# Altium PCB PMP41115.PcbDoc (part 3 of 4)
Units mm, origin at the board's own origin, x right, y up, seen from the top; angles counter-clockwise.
Board outline 97.92 x 43.13 mm, 4 copper layers (Top Layer, Signal Layer 1, Signal Layer 2, Bottom Layer), stack 1.016 mm thick; 168 components, 122 nets, 522 pads, 2459 vias.
Unrouted connection lines stored in the file: 1.
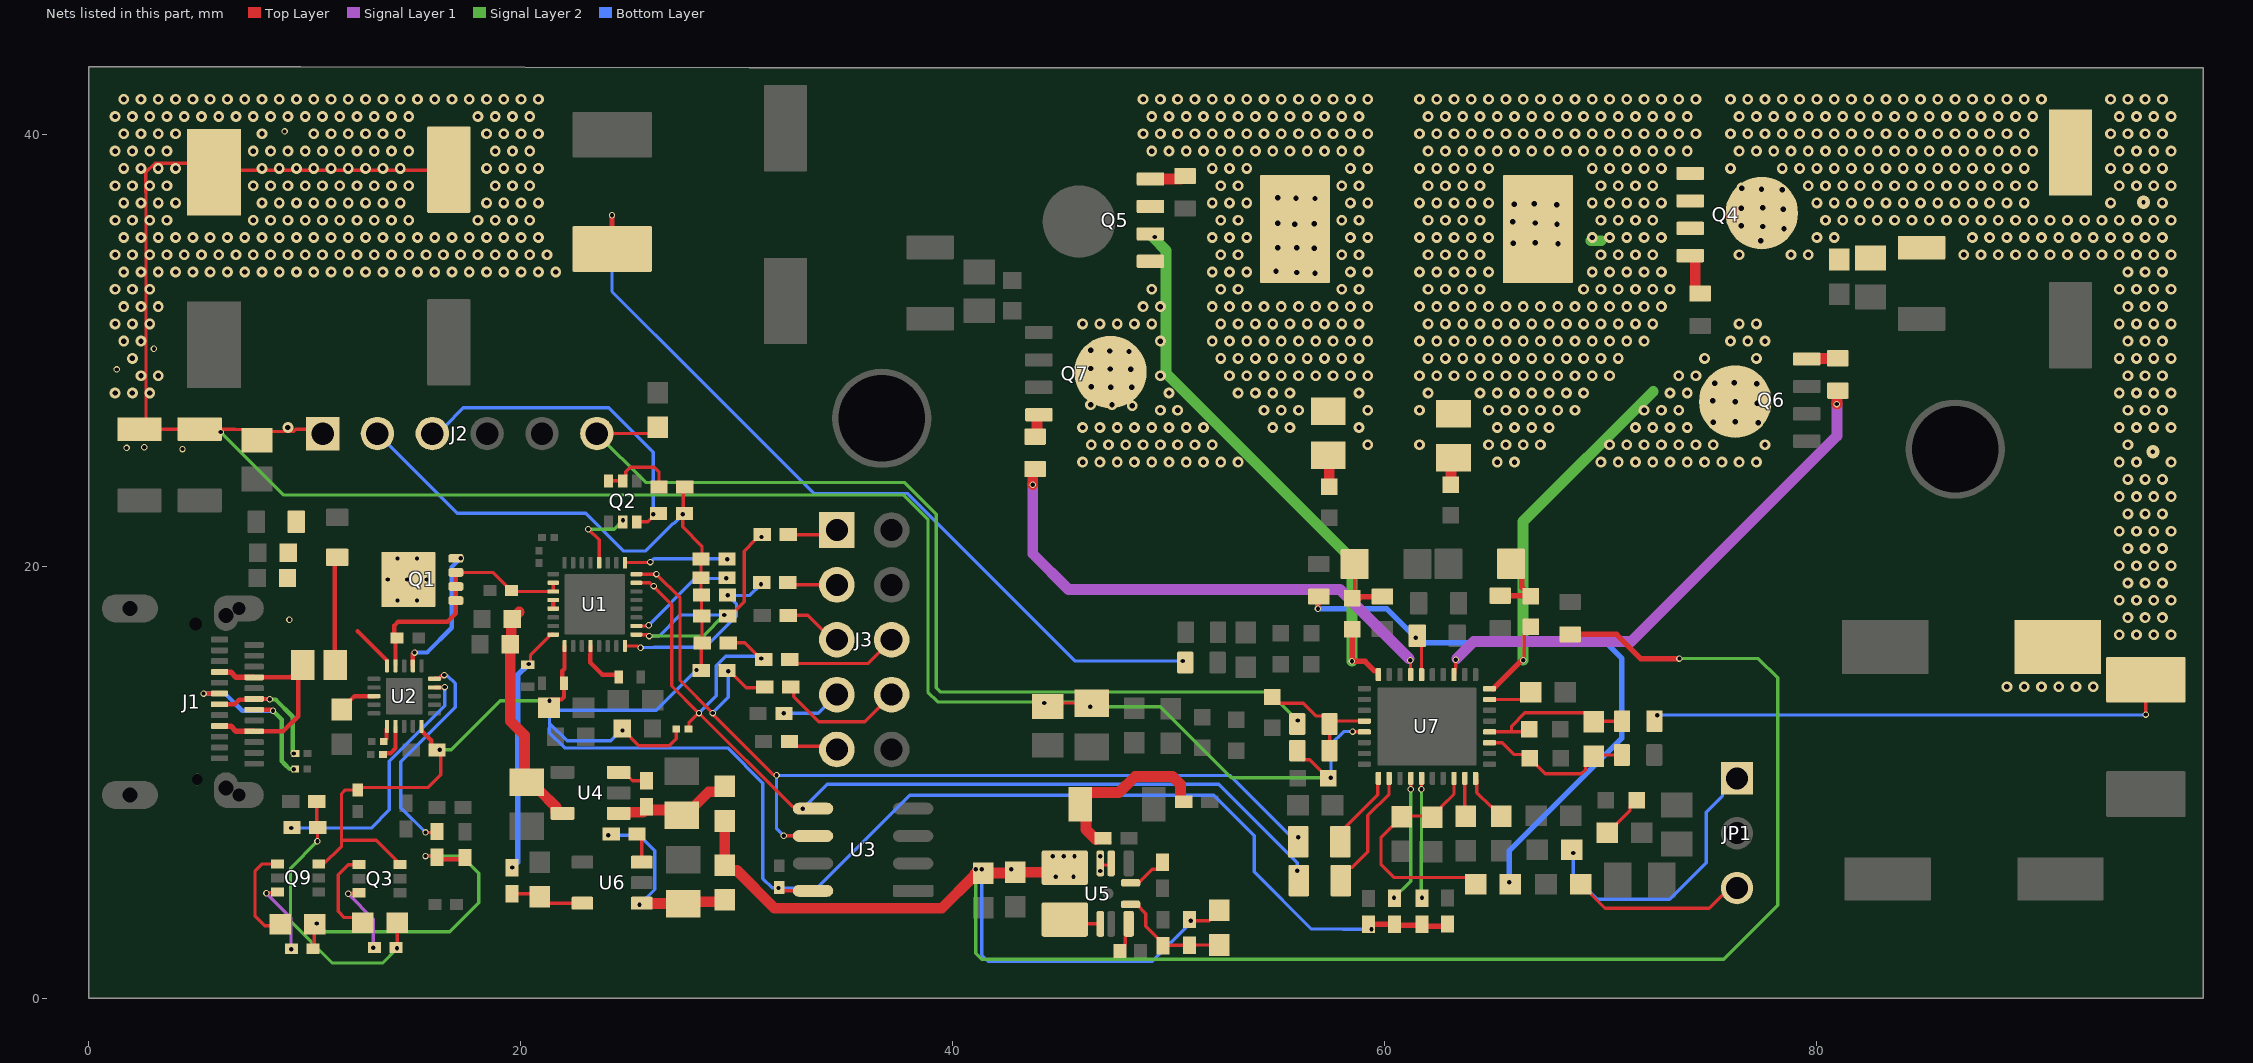
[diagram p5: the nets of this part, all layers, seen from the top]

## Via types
v1: diameter 0.5, hole 0.25, Top Layer to Bottom Layer, 2147 vias
v2: diameter 0.3, hole 0.2, Top Layer to Bottom Layer, tented both sides, 193 vias
v3: diameter 0.5, hole 0.25, Top Layer to Bottom Layer, tented both sides, 61 vias
v4: diameter 0.5, hole 0.2, Top Layer to Bottom Layer, 22 vias
v5: diameter 0.5, hole 0.2, Top Layer to Bottom Layer, tented both sides, 19 vias
v6: diameter 0.61, hole 0.203, Top Layer to Bottom Layer, tented both sides, 13 vias
v7: diameter 0.35, hole 0.2, Top Layer to Bottom Layer, tented both sides, 2 vias
v8: diameter 0.4, hole 0.2, Top Layer to Bottom Layer, tented both sides, 2 vias

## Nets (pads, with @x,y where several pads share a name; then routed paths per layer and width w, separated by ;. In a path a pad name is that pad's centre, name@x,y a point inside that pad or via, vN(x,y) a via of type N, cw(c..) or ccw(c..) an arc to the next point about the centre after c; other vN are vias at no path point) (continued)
I2Cc_SCL: R6.1 R64.2 R109.2 U1.16 U3.6 | length 46.7
  Top Layer w0.152: U1.16@25.36,19.632 25.361,19.633 26.288,19.633 v2(26.289,19.634) 27.381,18.542 27.381,14.707 v2@28.891,13.196 ; v2(28.895,13.2) 28.895,13.16 28.969,13.086 28.969,13.08 31.708,10.341 31.823,10.341 v2(31.852,10.312) ; R6.1@29.561,15.164 29.661,15.164 30.449,14.376 R109.2@31.013,14.376 ; v2(32.182,7.518) 32.188,7.512 32.874,7.512 U3.6@32.893,7.493 ; U3.6@32.87,7.687 33.051,7.506 U3.6@33.541,7.506 ; U3.6@33.985,7.518 U3.6@34.318,7.518
  Bottom Layer w0.152: v2@28.905,13.208 28.905,13.21 29.618,13.923 v2(29.618,15.142) ; v2@32.196,7.544 32.156,7.544 31.852,7.849 v2(31.852,10.312) 52.832,10.312 55.702,7.442 v2(56.007,7.442)
I2Cc_SDA: R7.1 R12.1 R60.2 R63.2 U1.15 U3.5 | length 47.5
  Top Layer w0.152: U1.15@25.476,19.228 25.984,19.228 27,18.212 27,14.453 v2@28.232,13.221 ; R12.1@27.768,12.458 27.793,12.483 27.793,12.757 28.232,13.196 v2@28.219,13.208 ; v2(28.26,13.2) 32.609,8.851 U3.5@33.06,8.851 ; R7.1@29.617,16.45 30.383,16.45 31.111,15.723 v2(31.14,15.723) ; v2(33.06,8.769) U3.5@33.06,8.851 ; U3.5@33.541,8.776 33.466,8.851 U3.5@33.06,8.851
  Bottom Layer w0.152: v2@28.245,13.208 28.268,13.208 29.058,13.998 29.058,15.392 29.491,15.826 30.997,15.826 31.1,15.723 v2(31.14,15.723) ; v2(33.06,8.769) 34.198,9.906 52.324,9.906 55.956,6.274 v2(55.956,5.893)
  other v2: 26.163,19.079
I2Ct_SCL: R3.1 R18.1 U1.9 | length 12.9
  Top Layer w0.152: U1.9@25.324,16.84 25.345,16.819 25.864,16.819 25.919,16.764 v2(25.959,16.764) ; R3.1@29.591,17.685 29.691,17.685 30.093,18.088 30.353,18.347 30.353,20.701 30.871,21.219 30.871,21.235 31.099,21.463 R18.1@31.115,21.463
  Signal Layer 2 w0.152: v2(25.959,16.764) 28.455,16.764 v2(29.432,17.741)
  Bottom Layer w0.152: v2(25.959,16.764) 26.416,16.764 27.393,17.741 v2(29.432,17.741)
  other v2: 31.155,21.353
I2Ct_SDA: R4.1 R20.1 U1.8 | length 8.8
  Top Layer w0.152: U1.8@24.835,16.307 25.437,16.307 25.487,16.256 v2@25.552,16.256 ; v2@25.512,16.231 v2(25.552,16.231) ; R20.1@31.048,19.228 R20.1@31.166,19.228
  Bottom Layer w0.152: v2(25.552,16.231) 26.153,16.231 26.175,16.253 28.546,16.253 29.997,17.704 29.997,18.242 v2@29.621,18.618 ; v2(29.592,18.647) 30.608,18.647 31.09,19.128 v2@31.09,19.177
  other v2: 31.13,19.169
I\2\C\c\_\I\R\Q\: R8.1 U1.17 | length 4.8
  Top Layer w0.152: U1.17@24.841,20.218 24.841,20.192 24.859,20.175 25.991,20.175 v2(26.01,20.193)
  Bottom Layer w0.152: v2(26.01,20.193) 26.02,20.193 26.173,20.345 v2@29.549,20.345
  other v2: 29.567,20.323
I\2\C\t\_\I\R\Q\: R5.1 U1.10 | length 5.2
  Top Layer w0.152: U1.10@25.36,17.232 25.853,17.232 25.908,17.287 v2@25.908,17.297
  Bottom Layer w0.152: v2(25.933,17.272) 28.096,19.434 29.493,19.434 v2@29.54,19.482 ; v2(29.516,19.434) 29.544,19.434 v2@29.566,19.456
ICHG: R71.2 U7.9 | length 1.6
  Top Layer w0.152: U7.9@63.754,10.008 63.718,9.972 63.718,8.479 R71.2@63.767,8.43
ILIM_HIZ: R65.2 U7.10 | length 2.3
  Top Layer w0.152: U7.10@64.218,10.178 64.267,10.129 64.267,9.52 64.936,8.851 65.001,8.851 65.405,8.446 R65.2@65.405,8.382
LDO_1V5: C17.2 U1.4 | length 2.4
  Top Layer w0.2: U1.4@23.235,16.307 23.235,15.921 23.223,15.909 23.223,15.536 23.781,14.978 24.452,14.978 24.542,14.887 C17.2@24.542,14.864
LDO_3V3: C10.1 C12.1 C16.2 J2.2 Q3.6 Q9.6 R1.2 R2.2 R3.2 R4.2 R5.2 R6.2 R7.2 R8.2 R12.2 R13.2 R14.2 R67.2 R68.2 R69.2 R70.2 R97.2 U1.1 U2.10 U3.8 | length 120.5
  Top Layer w0.152: Q9.6@10.653,6.213 10.719,6.147 10.82,6.147 11.709,7.036 11.709,7.315 ; Q3.6@14.3,6.325 13.31,7.315 11.709,7.315 ; C10.1@16.307,11.328 16.307,10.338 15.723,9.754 12.575,9.754 R97.2@12.459,9.638 11.873,9.638 11.709,9.474 11.709,7.315 ; v2(24.714,12.395) 24.768,12.395 25.48,11.684 26.873,11.684 27.203,12.014 R12.2@27.203,12.421 ; R2.2@27.505,22.367 27.505,21.82 28.397,20.927 R8.2@28.397,20.345 ; v2(27.508,22.403) 27.54,22.403 R2.2@27.587,22.45 27.529,22.508 27.529,23.59 R1.2@27.605,23.666 ; v2(28.143,15.189) 28.168,15.164 R6.2@28.361,15.164 28.361,16.394 R7.2@28.417,16.45 28.397,16.47 28.397,17.679 R3.2@28.391,17.685 28.379,17.697 R4.2@28.379,18.664 ; R4.2@28.354,18.664 R8.2@28.354,20.334 ; C12.1@31.902,5.055 31.991,4.966 U3.8@33.541,4.966
  Top Layer w0.2: U2.10@15.41,12.584 15.41,12.384 15.413,12.384 15.861,11.935 15.861,11.683 16.089,11.455 C10.1@16.154,11.455 ; v2(21.336,13.767) 21.393,13.823 21.894,13.823 22.011,13.941 C16.2@22.011,14.578 21.935,14.655 21.935,15.158 22.035,15.258 U1.1@22.035,16.307
  Top Layer w0.254: R68.2@59.254,3.415 59.434,3.415 59.443,3.423 R69.2@60.47,3.423 ; R69.2@60.47,3.38 61.701,3.38 R70.2@61.743,3.423 61.835,3.331 62.821,3.331 R67.2@62.921,3.431
  Signal Layer 2 w0.152: v2(16.256,11.506) 16.789,11.506 17.951,12.668 19.05,13.767 v2(21.336,13.767)
  Bottom Layer w0.152: J2.2@13.437,26.035 13.477,26.035 17.058,22.454 23.012,22.454 24.765,20.701 25.781,20.701 27.055,21.975 27.081,21.975 v2(27.508,22.403) ; v2@24.663,12.395 24.663,12.384 24.646,12.367 24.635,12.367 24.181,11.913 22.149,11.913 21.336,12.725 ; v2(28.143,15.189) 26.289,13.335 21.793,13.335 21.361,13.767 v2(21.336,13.767) 21.336,12.725 ; v2@31.902,5.105 31.648,5.105 31.217,5.537 31.217,9.957 29.591,11.582 22.047,11.582 21.336,12.294 21.336,12.725 ; v2(31.943,5.097) 33.723,5.097 38.024,9.398 52.095,9.398 53.975,7.518 53.975,5.842 56.617,3.2 58.09,3.2 ; 58.09,3.192 v2(59.4,3.192)
LODRV1: R43.1 U7.25 | length 24
  Top Layer w0.152: v2(61.189,15.646) 61.203,15.632 61.203,15.124 U7.25@61.214,15.113
  Top Layer w0.254: R43.1@43.788,24.462 R43.1@43.822,24.496
  Top Layer w0.5: v2(43.713,23.774) 43.713,24.384 R43.1@43.79,24.46
  Signal Layer 1 w0.254: v2@61.125,15.71 v2(61.189,15.646)
  Signal Layer 1 w0.5: v2(43.713,23.774) 43.713,20.574 45.364,18.923 57.937,18.923 v2@61.138,15.723
LODRV2: R44.1 U7.21 | length 24.6
  Top Layer w0.152: U7.21@63.218,14.978 63.267,15.027 63.267,15.261 63.297,15.291 v2(63.297,15.672)
  Top Layer w0.5: v2(80.95,27.508) 80.95,28.003 80.988,28.042 R44.1@81.001,28.042
  Signal Layer 1 w0.5: v2@63.348,15.723 64.135,16.51 71.425,16.51 80.95,26.035 v2(80.95,27.508)
MODE: R61.2 U7.17 | length 1.8
  Top Layer w0.152: U7.17@64.868,13.828 66.354,13.828 66.573,14.047 R61.2@66.573,14.097
NetC6_2: C6.2 R54.2 R56.2 U7.32 | length 5.9
  Top Layer w0.152: C6.2@54.796,13.942 55.083,13.655 56.235,13.655 56.822,13.068 57.162,13.068 57.46,12.769 R56.2@57.46,12.693 ; R56.2@57.429,12.522 57.461,12.491 R54.2@57.461,11.463 ; R56.2@57.506,12.828 U7.32@59.068,12.828
NetC7_1: 
NetC11_2: C11.2 U2.3 | length 1.8
  Top Layer w0.2: C11.2@11.717,13.363 11.717,13.388 12.312,13.984 U2.3@13.21,13.984
NetC19_1: C19.1 R21.2 R22.2 U4.1 | length 5.2
  Top Layer w0.152: U4.1@24.486,8.484 U4.1@24.54,8.484
  Top Layer w0.5: U4.1@24.54,8.553 24.59,8.603 25.666,8.603 25.776,8.712 R22.2@25.832,8.712 ; R22.2@25.875,8.712 C19.1@27.306,8.712 ; C19.1@27.46,8.464 27.626,8.464 28.715,9.553 29.23,9.553 29.286,9.61 R21.2@29.286,9.677
NetC21_1: C21.1 C22.1 R23.1 U5.2 U5.3 | length 9.6
  Top Layer w0.152: U5.3@46.845,6.239 46.919,6.165 47.272,6.165 U5.2@47.345,6.239
  Top Layer w0.254: U5.3@46.845,6.239 v7(46.845,6.569) ; C22.1@46.97,7.402 47.07,7.402 C22.1@47.243,7.229 ; U5.2@47.297,6.287 U5.2@47.345,6.239
  Top Layer w0.5: C22.1@46.641,7.348 46.175,7.813 46.175,8.712 C21.1@45.919,8.968 45.919,9.218 46.219,9.518 47.713,9.518 48.456,10.262 50.19,10.262 50.557,9.895 50.557,9.142 50.607,9.092 R23.1@50.707,9.092
  other v7: 46.845,5.889
NetC23_1: C23.1 U5.8 | length 1.4
  Top Layer w0.152: C23.1@47.748,2.184 47.976,2.412 47.976,2.499 48.004,2.527 48.004,2.826 48.011,2.832 48.011,3.292 U5.8@48.157,3.439
NetC24_2: C24.2 R24.1 R29.2 U5.9 | length 5.1
  Top Layer w0.152: U5.9@48.245,4.339 48.52,4.339 48.946,3.913 48.946,3.33 R29.2@49.752,2.523 ; R29.2@49.835,2.489 49.881,2.443 C24.2@50.965,2.443 ; C24.2@51.003,2.464 52.348,2.464 R24.1@52.352,2.46
NetC27_1: C27.1 R26.2 U6.5 | length 3.3
  Top Layer w0.152: R26.2@19.594,4.833 20.784,4.833 C27.1@20.803,4.851 ; C27.1@20.904,4.597 21.108,4.394 U6.5@22.862,4.394
NetC28_1: C28.1 R25.2 R27.2 U6.1 | length 9.2
  Top Layer w0.152: v2(25.502,4.318) 25.577,4.394 U6.1@25.612,4.394 ; R25.2@29.337,4.496 29.391,4.496 R25.2@29.452,4.557
  Top Layer w0.5: U6.1@25.612,4.394 25.621,4.384 C28.1@27.391,4.384 ; C28.1@27.531,4.375 27.622,4.466 29.24,4.466 R25.2@29.337,4.369
  Bottom Layer w0.152: v2(24.054,7.544) 25.502,7.544 26.213,6.833 26.213,5.029 v2(25.502,4.318)
NetC36_1: C36.1 R41.1 | length 1.4
  Top Layer w0.5: C36.1@57.379,23.774 57.412,23.774 57.442,23.804 57.442,25.099 R41.1@57.406,25.134
NetC37_1: C37.1 R42.1 | length 1.3
  Top Layer w0.5: C37.1@63.077,23.779 63.077,24.899 R42.1@63.198,25.02
NetC40_2: C40.2 D3.1 R49.2 | length 3.1
  Top Layer w0.152: C40.2@58.507,18.513 58.622,18.628 D3.1@58.622,20.096
  Top Layer w0.254: C40.2@58.507,18.513 58.533,18.487 58.812,18.487 58.915,18.59 R49.2@59.903,18.59
NetC41_1: C41.1 D4.1 R50.2 | length 3.1
  Top Layer w0.254: R50.2@65.362,18.635 C41.1@66.641,18.635 ; D4.1@65.862,20.114 66.349,19.627 66.349,19.033 66.726,18.657 C41.1@66.726,18.644
NetC42_1: C42.1 R51.1 | length 2
  Top Layer w0.152: R51.1@70.315,7.656 70.34,7.656 71.373,8.688 71.373,8.889 C42.1@71.577,9.093
NetC67_1: 
NetC67_2: 
NetJ3_1: J3.1 R18.2 | length 2
  Top Layer w0.152: R18.2@32.395,21.459 34.362,21.459 J3.1@34.417,21.514
NetJ3_3: J3.3 R20.2 | length 2.1
  Top Layer w0.152: R20.2@32.369,19.249 32.485,19.134 34.399,19.134 J3.3@34.417,19.152
NetJ3_5: J3.5 R48.2 | length 2.3
  Top Layer w0.152: R48.2@32.395,17.725 33.304,17.725 J3.5@34.29,16.739
NetJ3_6: J3.6 R60.1 | length 4.9
  Top Layer w0.152: R60.1@32.458,15.676 32.641,15.493 36.08,15.493 36.945,16.358 J3.6@36.957,16.358
NetJ3_7: J3.7 R66.2 | length 2.5
  Bottom Layer w0.152: v2(32.183,13.186) 33.774,13.186 34.366,13.778 J3.7@34.366,13.843
NetJ3_8: J3.8 R109.1 | length 6
  Top Layer w0.152: R109.1@32.502,14.402 32.647,14.258 32.647,13.962 33.807,12.802 35.929,12.802 J3.8@37.182,14.054
NetJ3_9: J3.9 R110.2 | length 2.2
  Top Layer w0.152: R110.2@32.452,11.887 32.675,11.663 34.565,11.663 J3.9@34.595,11.633
NetJP1_1: JP1.1 R58.2 | length 12.7
  Bottom Layer w0.152: JP1.1@76.29,10.211 JP1.1@76.325,10.175
  Bottom Layer w0.154: v2(68.747,6.723) 68.747,5.675 69.85,4.572 73.203,4.572 74.905,6.274 74.905,8.611 75.652,9.358 75.652,9.502 76.081,9.931 JP1.1@76.225,9.931
NetJP1_3: JP1.3 R59.2 | length 8.1
  Top Layer w0.152: R59.2@69.082,5.272 69.107,5.272 70.213,4.166 75.031,4.166 75.961,5.095 JP1.3@76.325,5.095
NetQ1_4: Q1.4 U2.17 | length 6.3
  Top Layer w0.2: U2.17@15.01,15.384 15.01,15.936 v2@15.127,16.053
  Bottom Layer w0.2: v2(15.088,16.002) 15.672,16.002 16.815,17.145 16.815,19.964 v2(17.221,20.371)
NetQ2_2: Q2.2 U1.20 | length 3.5
  Top Layer w0.152: v2(23.139,21.717) 23.635,21.221 U1.20@23.635,20.157 ; Q2.2@24.663,22.123 Q2.2@24.689,22.098
  Signal Layer 2 w0.152: v2(23.139,21.717) 24.333,21.717 24.691,22.075 24.691,22.095 v2@24.689,22.098
  other v2: 24.74,22.123
NetQ2_5: Q2.5 Q2.6 R1.1 | length 3.3
  Top Layer w0.152: Q2.6@24.079,23.952 24.537,23.952 Q2.5@24.562,23.927 ; Q2.5@24.74,24.13 24.817,24.13 24.863,24.176 24.863,24.38 25.07,24.587 26.187,24.587 26.405,24.37 R1.1@26.405,23.666
NetQ3_1: Q3.1 R102.2 | length 3.8
  Top Layer w0.152: R102.2@12.344,3.683 12.297,3.73 11.84,3.73 11.551,4.019 11.551,5.709 12.019,6.177 Q3.1@12.517,6.177
NetQ3_3: Q3.3 R106.1 | length 3.3
  Top Layer w0.152: v2(12.014,4.826) 12.04,4.852 12.294,4.852 Q3.3@12.294,4.801
  Signal Layer 1 w0.152: v2(12.014,4.826) 13.183,3.658 v2(13.183,2.337)
NetQ4_4: Q4.4 R34.1 | length 2.1
  Top Layer w0.5: Q4.4@74.158,34.378 74.332,34.378 74.387,34.323 74.387,32.748 74.512,32.623 R34.1@74.615,32.623
NetQ5_4: Q5.4 R37.1 | length 1.6
  Top Layer w0.152: R37.1@50.571,37.961 50.711,37.961 R37.1@50.775,38.024
  Top Layer w0.5: Q5.4@49.164,37.929 50.565,37.929 R37.1@50.571,37.922
NetQ6_4: Q6.4 R44.2 | length 1.4
  Top Layer w0.5: Q6.4@79.555,29.596 79.572,29.612 80.869,29.612 R44.2@80.899,29.642
NetQ7_4: Q7.4 R43.2 | length 1.1
  Top Layer w0.5: R43.2@43.822,25.996 43.91,26.084 43.91,26.958 43.965,27.013 Q7.4@43.998,27.013
NetQ8_1: 
NetQ8_2: 
NetQ8_4: 
NetQ9_1: Q9.1 R101.2 | length 4.2
  Top Layer w0.152: R101.2@8.484,3.353 8.153,3.353 7.696,3.81 7.696,5.867 8.041,6.213 Q9.1@8.753,6.213
NetQ9_3: Q9.3 R105.1 | length 3.5
  Top Layer w0.152: v2(8.23,4.851) 8.258,4.88 8.588,4.88 Q9.3@8.611,4.902
  Signal Layer 1 w0.152: v2(8.23,4.851) 9.373,3.708 v2(9.373,2.261) 9.373,2.235 v2@9.347,2.21
NetR9_2: 
NetR10_1: R10.1 U2.7 | length 1.7
  Top Layer w0.2: R10.1@13.624,11.271 13.684,11.331 13.973,11.331 14.21,11.568 U2.7@14.21,12.584
NetR11_1: R11.1 U2.6 | length 0.6
  Top Layer w0.2: R11.1@13.663,11.887 13.683,11.887 13.792,11.996 U2.6@13.792,12.471
NetR22_1: R22.1 U4.3 | length 1.4
  Top Layer w0.152: U4.3@24.54,10.453 24.79,10.453 25.181,10.062 R22.1@25.825,10.062
NetR27_1: R27.1 U6.3 | length 1.4
  Top Layer w0.152: R27.1@25.391,7.6 25.612,7.38 25.612,6.358 U6.3@25.552,6.299
NetR28_2: R28.2 U5.11 | length 2
  Top Layer w0.152: U5.11@48.245,5.339 48.269,5.315 48.589,5.315 49.237,5.963 49.49,5.963 49.657,6.13 R28.2@49.657,6.35
NetR63_1: R63.1 U7.2 | length 5.6
  Top Layer w0.152: R63.1@57.984,5.44 57.984,5.665 58.383,6.063 58.514,6.063 59.233,6.782 59.233,8.46 60.213,9.44 60.213,9.954 60.218,9.959 U7.2@60.218,10.003
NetR64_1: R64.1 U7.1 | length 3.7
  Top Layer w0.152: R64.1@57.955,7.242 58.201,7.488 58.201,7.926 59.69,9.415 U7.1@59.69,10.236
NetR72_1: 
NetR73_1: 
NetR99_2: R99.2 R101.1 R103.2 R105.2 | length 15.2
  Top Layer w0.152: R105.2@10.386,2.285 10.386,2.359 10.439,2.413 R101.1@10.439,3.277 ; v2(15.596,6.579) 16.027,6.579 R103.2@16.053,6.553
  Top Layer w0.2: R103.2@16.133,6.517 16.219,6.431 17.357,6.431 R99.2@17.433,6.507
  Signal Layer 2 w0.152: v2(10.566,3.454) 10.947,3.073 16.713,3.073 18.059,4.42 18.059,5.778 17.259,6.579 15.664,6.579 15.621,6.621 v2@15.621,6.629
NetR100_1: R100.1 R102.1 R104.1 R106.2 | length 13.3
  Top Layer w0.152: R104.1@10.289,7.679 10.513,7.903 R104.1@10.613,7.903 ; R104.1@10.465,7.976 10.562,8.073 R100.1@10.562,9.107 ; v2(10.592,7.264) R104.1@10.592,7.722 ; R106.2@14.249,2.438 14.283,2.472 R102.1@14.283,3.48
  Signal Layer 2 w0.152: v2(10.592,7.264) 9.347,6.02 9.347,3.556 11.278,1.626 13.614,1.626 v2@14.274,2.286
  other v2: 14.275,2.311
NetU5_5: U5.5 U5.6 | length 1.7
  Top Layer w0.152: U5.5@45.195,3.639 45.393,3.441 46.843,3.441 U5.6@46.845,3.439
P_OUT: C51.2 C52.2 C53.1 C54.1 C62.1 Q4.5-6-7-8 R33.1 R35.1 | length 23.4
  Top Layer w0.152: v2(95.25,13.132) R33.1@95.25,13.894
  Bottom Layer w0.152: v2@72.644,13.106 95.225,13.106 v2(95.25,13.132)
  other v1: 88.823,14.421 89.623,14.421 90.423,14.421 91.223,14.421 92.023,14.421 92.823,14.421 94.023,16.821 94.823,16.821 95.623,16.821 96.423,16.821 94.423,17.621 95.223,17.621 96.023,17.621 94.023,18.421 94.823,18.421 95.623,18.421 96.423,18.421 94.423,19.221 95.223,19.221 96.023,19.221 94.023,20.021 94.823,20.021 95.623,20.021 96.423,20.021 94.423,20.821 95.223,20.821 96.023,20.821 94.023,21.621 94.823,21.621 95.623,21.621 96.423,21.621 94.423,22.421 95.223,22.421 96.023,22.421 94.023,23.221 94.823,23.221 95.623,23.221 96.423,23.221 94.423,24.021 95.223,24.021 96.023,24.021 94.023,24.821 94.823,24.821 96.423,24.821 94.423,25.621 94.023,26.421 94.823,26.421 95.623,26.421 96.423,26.421 94.423,27.221 95.223,27.221 96.023,27.221 94.023,28.021 94.823,28.021 95.623,28.021 96.423,28.021 94.423,28.821 95.223,28.821 96.023,28.821 94.023,29.621 94.823,29.621 95.623,29.621 96.423,29.621 94.423,30.421 95.223,30.421 96.023,30.421 94.023,31.221 94.823,31.221 95.623,31.221 96.423,31.221 94.423,32.021 95.223,32.021 96.023,32.021 94.023,32.821 94.823,32.821 95.623,32.821 96.423,32.821 94.423,33.621 95.223,33.621 96.023,33.621 76.423,34.421 78.823,34.421 79.623,34.421 86.823,34.421 87.623,34.421 88.423,34.421 89.223,34.421 90.023,34.421 90.823,34.421 91.623,34.421 92.423,34.421 93.223,34.421 94.023,34.421 94.823,34.421 95.623,34.421 96.423,34.421 80.023,35.221 80.823,35.221 87.223,35.221 88.023,35.221 88.823,35.221 89.623,35.221 90.423,35.221 91.223,35.221 92.023,35.221 92.823,35.221 93.623,35.221 94.423,35.221 95.223,35.221 96.023,35.221 80.423,36.021 81.223,36.021 82.023,36.021 82.823,36.021 83.623,36.021 84.423,36.021 85.223,36.021 86.023,36.021 86.823,36.021 87.623,36.021 88.423,36.021 89.223,36.021 90.023,36.021 90.823,36.021 91.623,36.021 92.423,36.021 93.223,36.021 94.023,36.021 94.823,36.021 95.623,36.021 96.423,36.021 80.023,36.821 80.823,36.821 81.623,36.821 82.423,36.821 83.223,36.821 84.023,36.821 84.823,36.821 85.623,36.821 86.423,36.821 87.223,36.821 88.023,36.821 88.823,36.821 89.623,36.821 93.623,36.821 96.023,36.821 79.623,37.621 80.423,37.621 81.223,37.621 82.023,37.621 82.823,37.621 83.623,37.621 84.423,37.621 85.223,37.621 86.023,37.621 86.823,37.621 87.623,37.621 88.423,37.621 89.223,37.621 90.023,37.621 94.023,37.621 94.823,37.621 95.623,37.621 96.423,37.621 76.023,38.421 78.423,38.421 79.223,38.421 80.023,38.421 80.823,38.421 81.623,38.421 82.423,38.421 83.223,38.421 84.023,38.421 84.823,38.421 85.623,38.421 86.423,38.421 87.223,38.421 88.023,38.421 88.823,38.421 89.623,38.421 93.623,38.421 94.423,38.421 95.223,38.421 96.023,38.421 76.423,39.221 77.223,39.221 78.023,39.221 78.823,39.221 79.623,39.221 80.423,39.221 81.223,39.221 82.023,39.221 82.823,39.221 83.623,39.221 84.423,39.221 85.223,39.221 86.023,39.221 86.823,39.221 87.623,39.221 88.423,39.221 89.223,39.221 90.023,39.221 94.023,39.221 94.823,39.221 95.623,39.221 96.423,39.221 76.023,40.021 76.823,40.021 77.623,40.021 78.423,40.021 79.223,40.021 80.023,40.021 80.823,40.021 81.623,40.021 82.423,40.021 83.223,40.021 84.023,40.021 84.823,40.021 85.623,40.021 86.423,40.021 87.223,40.021 88.023,40.021 88.823,40.021 89.623,40.021 93.623,40.021 94.423,40.021 95.223,40.021 96.023,40.021 76.423,40.821 77.223,40.821 78.023,40.821 78.823,40.821 79.623,40.821 80.423,40.821 81.223,40.821 82.023,40.821 82.823,40.821 83.623,40.821 84.423,40.821 85.223,40.821 86.023,40.821 86.823,40.821 87.623,40.821 88.423,40.821 89.223,40.821 90.023,40.821 94.023,40.821 94.823,40.821 95.623,40.821 96.423,40.821 76.023,41.621 76.823,41.621 77.623,41.621 78.423,41.621 79.223,41.621 80.023,41.621 80.823,41.621 81.623,41.621 82.423,41.621 83.223,41.621 84.023,41.621 84.823,41.621 85.623,41.621 86.423,41.621 87.223,41.621 88.023,41.621 88.823,41.621 89.623,41.621 90.423,41.621 93.623,41.621 94.423,41.621 95.223,41.621 96.023,41.621
  other v2: 72.634,13.098
  other v3: 77.432,35.071 78.499,35.63 77.508,35.731 76.518,35.757 78.473,36.519 76.518,36.57 77.508,36.595 78.423,37.433 77.457,37.459 76.543,37.509
  other v6: 95.58,25.298 95.148,36.855
PD_D_N: J1.A7 J1.B7 R19.2 | length 8.4
  Top Layer w0.2: v2(5.318,14.103) J1.B7@6.058,14.103 ; J1.A7@7.658,13.353 8.464,13.353 8.507,13.31 v2(8.534,13.31)
  Signal Layer 2 w0.2: v2(8.534,13.31) 8.941,12.903 8.941,10.973 9.082,10.831 9.303,10.611 9.48,10.611 v2(9.5,10.592)
  Bottom Layer w0.2: v2(5.318,14.103) 6.309,14.103 7.11,13.303 8.527,13.303 v2(8.534,13.31)
PD_D_P: J1.A6 J1.B6 R17.2 | length 5.5
  Top Layer w0.2: J1.B6@6.058,13.603 6.758,13.603 6.973,13.818 7.623,13.818 J1.A6@7.658,13.853 8.336,13.853 8.357,13.833 v2@8.357,13.818
  Signal Layer 2 w0.2: v2(8.382,13.843) 8.401,13.824 8.657,13.824 9.449,13.032 v2@9.449,11.354
  other v2: 9.5,11.328
PP5V: C13.1 C14.1 C20.1 U1.28 U1.29 U4.5 | length 11.3
  Top Layer w0.2: U1.28@21.488,18.415 21.51,18.393 U1.29@21.51,18.032
  Top Layer w0.5: C14.1@19.939,17.882 19.786,17.729 19.761,17.729 19.611,17.579 C14.1@19.611,17.554 19.564,17.506 19.564,16.427 C13.1@19.516,16.379 19.516,16.206 19.519,16.204 19.519,12.828 20.176,12.17 C20.1@20.176,10.091 ; C20.1@20.278,9.99 C20.1@20.176,10.091 ; U4.5@21.94,8.553 21.69,8.553 21.64,8.603 21.64,8.853 20.888,9.605 20.663,9.605 C20.1@20.176,10.091
PP7V: C24.1 C25.1 C26.1 R21.1 R24.2 R25.1 R55.1 U5.4 | length 99.1
  Top Layer w0.152: U5.4@44.298,5.929 45.085,5.929 U5.4@45.195,6.039 ; v2(51.029,3.581) 51.899,3.581 52.222,3.905 R24.2@52.222,4.064
  Top Layer w0.254: 40.945,5.79 40.945,5.83 41.072,5.957 v2(41.072,5.969) ; R55.1@68.595,16.841 70.749,16.841 71.867,15.723 v2(73.66,15.723)
  Top Layer w0.5: R25.1@29.453,6.291 29.453,8.202 R21.1@29.455,8.203 ; R25.1@29.479,6.291 29.479,6.105 29.677,5.907 30.015,5.907 31.757,4.166 39.497,4.166 40.945,5.613 41.247,5.613 C25.1@41.423,5.79 ; v2(41.351,5.969) 41.351,5.862 C25.1@41.423,5.79 ; C26.1@42.723,5.79 C25.1@41.423,5.79 ; C26.1@42.906,5.827 44.196,5.827 U5.4@44.298,5.929
  Signal Layer 2 w0.152: v2(41.072,5.969) 41.072,2.082 41.35,1.803 75.717,1.803 78.207,4.293 78.207,14.834 77.318,15.723 v2(73.66,15.723)
  Bottom Layer w0.152: v2(41.072,5.969) v2@41.326,5.969 ; v2(41.351,5.969) 41.351,1.993 41.643,1.702 49.251,1.702 v2@51.079,3.531
  other v2: 42.723,5.969
  other v5: 44.785,5.619 45.605,5.619 44.645,6.569 45.145,6.569 45.645,6.569
PP_EN: J2.3 Q2.3 R2.1 | length 15.2
  Top Layer w0.152: Q2.3@25.379,22.052 25.889,22.052 26.24,22.403 R2.1@26.264,22.403
  Bottom Layer w0.152: J2.3@16.027,26.467 16.485,26.467 17.348,27.33 24.079,27.33 26.137,25.273 v2(26.137,22.403)
PPHV: C31.2 C44.2 C45.1 C55.2 C56.1 C57.1 C59.1 J2.1 R30.1 R31.2 R45.2 R54.1 U7.33 | length 144.7
  Top Layer w0.152: C31.2@2.349,26.339 C31.2@2.654,26.339 ; J2.1@10.831,26.141 10.626,26.346 9.582,26.346 9.47,26.234 9.223,26.234 8.193,26.234 C59.1@7.79,25.831 7.291,26.33 6.776,26.33 6.76,26.346 C56.1@5.138,26.346 5.135,26.342 2.658,26.342 C31.2@2.654,26.339 ; C55.2@16.675,38.365 16.65,38.339 14.423,38.339 13.623,38.339 12.823,38.339 12.023,38.339 11.223,38.339 10.423,38.339 9.623,38.339 8.823,38.339 8.023,38.339 5.888,38.339 C57.1@5.796,38.248 5.385,38.659 3.073,38.659 2.647,38.232 2.647,37.621 2.647,37.3 2.654,37.293 2.654,36.021 2.654,34.421 2.654,32.821 2.654,31.221 C31.2@2.654,26.339 ; v2(44.247,13.665) C45.1@44.406,13.506 44.565,13.665 46.252,13.665 R45.2@46.379,13.538 ; v2(46.38,13.487) R45.2@46.649,13.756 ; R54.1@55.663,11.887 55.73,11.82 55.73,11.57 R54.1@55.768,11.532 ; R54.1@55.905,11.532 R54.1@55.893,11.532 ; R54.1@55.962,11.463 R54.1@55.893,11.532 ; C44.2@57.4,10.182 56.542,11.039 56.26,11.039 R54.1@55.768,11.532 ; v2(58.522,12.344) 58.53,12.336 59.06,12.336 U7.33@59.068,12.328 ; R54.1@55.768,11.532 R54.1@55.893,11.532
  Top Layer w0.254: R30.1@24.155,35.509 24.232,35.585 v2(24.232,36.246)
  Signal Layer 2 w0.152: v2(6.121,26.213) 9.039,23.295 37.741,23.295 38.862,22.174 38.862,14.173 39.319,13.716 46.152,13.716 v2(46.38,13.487) 49.618,13.487 52.903,10.203 v2(57.521,10.203)
  Bottom Layer w0.152: v2(24.232,36.246) 24.232,32.715 28.169,28.778 33.579,23.368 37.897,23.368 45.652,15.613 v2(50.663,15.613) ; v2(57.521,10.203) 57.521,11.75 58.115,12.344 v2(58.522,12.344)
  other v1: 9.223,26.421 1.223,28.021 2.023,28.021 2.823,28.021 2.423,28.821 3.223,28.821 2.023,29.621 1.623,30.421 2.423,30.421 1.223,31.221 2.023,31.221 2.823,31.221 1.623,32.021 2.423,32.021 3.223,32.021 1.223,32.821 2.023,32.821 2.823,32.821 1.623,33.621 2.423,33.621 3.223,33.621 4.023,33.621 4.823,33.621 5.623,33.621 6.423,33.621 7.223,33.621 8.023,33.621 8.823,33.621 9.623,33.621 10.423,33.621 11.223,33.621 12.023,33.621 12.823,33.621 13.623,33.621 14.423,33.621 15.223,33.621 16.023,33.621 16.823,33.621 17.623,33.621 18.423,33.621 19.223,33.621 20.023,33.621 20.823,33.621 21.623,33.621 1.223,34.421 2.023,34.421 2.823,34.421 3.623,34.421 4.423,34.421 5.223,34.421 6.023,34.421 6.823,34.421 7.623,34.421 8.423,34.421 9.223,34.421 10.023,34.421 10.823,34.421 11.623,34.421 12.423,34.421 13.223,34.421 14.023,34.421 14.823,34.421 15.623,34.421 16.423,34.421 17.223,34.421 18.023,34.421 18.823,34.421 19.623,34.421 20.423,34.421 21.223,34.421 1.623,35.221 2.423,35.221 3.223,35.221 4.023,35.221 4.823,35.221 5.623,35.221 6.423,35.221 7.223,35.221 8.023,35.221 8.823,35.221 9.623,35.221 10.423,35.221 11.223,35.221 12.023,35.221 12.823,35.221 13.623,35.221 14.423,35.221 15.223,35.221 16.023,35.221 16.823,35.221 17.623,35.221 18.423,35.221 19.223,35.221 20.023,35.221 20.823,35.221 1.223,36.021 2.023,36.021 2.823,36.021 3.623,36.021 7.623,36.021 8.423,36.021 9.223,36.021 10.023,36.021 10.823,36.021 11.623,36.021 12.423,36.021 13.223,36.021 14.023,36.021 14.823,36.021 18.023,36.021 18.823,36.021 19.623,36.021 20.423,36.021 1.623,36.821 2.423,36.821 3.223,36.821 4.023,36.821 8.023,36.821 8.823,36.821 9.623,36.821 10.423,36.821 11.223,36.821 12.023,36.821 12.823,36.821 13.623,36.821 14.423,36.821 18.423,36.821 19.223,36.821 20.023,36.821 20.823,36.821 1.223,37.621 2.023,37.621 2.823,37.621 3.623,37.621 7.623,37.621 8.423,37.621 9.223,37.621 10.023,37.621 10.823,37.621 11.623,37.621 12.423,37.621 13.223,37.621 14.023,37.621 14.823,37.621 18.823,37.621 19.623,37.621 20.423,37.621 1.623,38.421 2.423,38.421 3.223,38.421 4.023,38.421 8.023,38.421 8.823,38.421 9.623,38.421 10.423,38.421 11.223,38.421 12.023,38.421 12.823,38.421 13.623,38.421 14.423,38.421 18.423,38.421 19.223,38.421 20.023,38.421 20.823,38.421 1.223,39.221 2.023,39.221 2.823,39.221 3.623,39.221 7.623,39.221 8.423,39.221 9.223,39.221 10.023,39.221 10.823,39.221 11.623,39.221 12.423,39.221 13.223,39.221 14.023,39.221 14.823,39.221 18.823,39.221 19.623,39.221 20.423,39.221 1.623,40.021 2.423,40.021 3.223,40.021 4.023,40.021 8.023,40.021 10.423,40.021 11.223,40.021 12.023,40.021 12.823,40.021 13.623,40.021 14.423,40.021 18.423,40.021 19.223,40.021 20.023,40.021 20.823,40.021 1.223,40.821 2.023,40.821 2.823,40.821 3.623,40.821 4.423,40.821 5.223,40.821 6.023,40.821 6.823,40.821 7.623,40.821 8.423,40.821 9.223,40.821 10.023,40.821 10.823,40.821 11.623,40.821 12.423,40.821 13.223,40.821 14.023,40.821 14.823,40.821 18.023,40.821 18.823,40.821 19.623,40.821 20.423,40.821 1.623,41.621 2.423,41.621 3.223,41.621 4.023,41.621 4.823,41.621 5.623,41.621 6.423,41.621 7.223,41.621 8.023,41.621 8.823,41.621 9.623,41.621 10.423,41.621 11.223,41.621 12.023,41.621 12.823,41.621 13.623,41.621 14.423,41.621 15.223,41.621 16.023,41.621 16.823,41.621 17.623,41.621 18.423,41.621 19.223,41.621 20.023,41.621 20.823,41.621
  other v2: 4.343,25.425 1.753,25.476 2.565,25.502 1.295,29.108 3.023,30.074 9.068,40.132
REGN: C46.1 R38.2 R53.1 U7.24 | length 30
  Top Layer w0.152: v2(61.443,16.688) 61.517,16.762 C46.1@61.517,16.776 61.718,16.574 61.718,15.015 U7.24@61.722,15.011
  Top Layer w0.254: v2(56.921,18.034) 56.921,18.415 R53.1@56.972,18.466
  Bottom Layer w0.254: v2(56.921,18.034) 60.096,18.034 v2(61.443,16.688) 61.671,16.459 70.256,16.459 70.993,15.723 70.993,12.04 65.786,6.833 v2(65.786,5.359) v2@65.799,5.347
SBU1: R103.1 U2.15 | length 10
  Top Layer w0.152: v2(15.596,7.671) 15.951,7.671 R103.1@15.977,7.696
  Top Layer w0.2: U2.15@16.01,14.784 16.21,14.784 16.317,14.891 16.362,14.891 16.432,14.961 v2(16.459,14.961)
  Bottom Layer w0.152: v2(15.596,7.671) 14.453,8.814 14.453,10.947 16.967,13.462 16.967,14.573 16.608,14.932 16.487,14.932 v2(16.459,14.961)
SBU2: R104.2 U2.14 | length 12.1
  Top Layer w0.2: U2.14@16.01,14.384 16.466,14.384 v2(16.485,14.402)
  Bottom Layer w0.152: v2(9.373,7.874) 13.081,7.874 13.919,8.712 13.919,10.973 16.485,13.538 v2(16.485,14.402)
SRN: C30.2 C35.1 R36.2 U7.13 | length 6.9
  Top Layer w0.152: U7.13@64.868,11.828 65.464,11.828 66.015,11.278 C35.1@66.751,11.278 ; C35.1@66.734,11.106 67.452,10.389 69.12,10.389 69.316,10.585 69.316,10.776 69.538,10.998 C30.2@69.748,10.998 ; C30.2@69.694,11.2 69.752,11.258 70.758,11.258 R36.2@70.79,11.227
SRP: C30.1 C34.1 R35.2 U7.14 | length 7.2
  Top Layer w0.152: U7.14@64.868,12.328 65.888,12.328 ; C34.1@66.715,12.454 66.589,12.328 65.888,12.328 ; C30.1@69.494,13.03 69.317,13.208 66.497,13.208 65.888,12.598 65.888,12.328 ; C30.1@69.926,12.852 69.956,12.823 R35.2@71.003,12.823
STAT1: R69.1 U7.4 | length 5.9
  Top Layer w0.152: v2@61.216,9.677 61.216,10.176 U7.4@61.218,10.178
  Signal Layer 2 w0.152: v2(60.442,4.64) 61.214,5.412 v2(61.214,9.677)
STAT2: R70.1 U7.5 | length 5.5
  Top Layer w0.152: v2@61.697,9.703 61.716,9.722 61.716,10.176 U7.5@61.718,10.178
  Signal Layer 2 w0.152: v2(61.714,9.677) 61.714,7.25 61.709,7.244 61.709,4.668 v2(61.737,4.64)
SW1: C40.1 L2.1 Q5.1 Q5.2 Q5.3 Q7.5-6-7-8 R41.2 U7.28 | length 26.5
  Top Layer w0.254: v2(58.496,15.596) 59.101,15.596 59.545,15.151 59.716,15.151 59.718,15.149 U7.28@59.718,14.978 ; v2@58.507,15.635 C40.1@58.507,17.09
  Signal Layer 2 w0.5: v2@49.301,35.204 49.886,34.62 49.886,28.931 58.496,20.32 v2(58.496,15.596)
  other v1: 46.023,24.821 46.823,24.821 47.623,24.821 48.423,24.821 49.223,24.821 50.023,24.821 50.823,24.821 51.623,24.821 52.423,24.821 53.223,24.821 46.423,25.621 47.223,25.621 48.023,25.621 48.823,25.621 49.623,25.621 50.423,25.621 51.223,25.621 52.023,25.621 59.223,25.621 46.023,26.421 46.823,26.421 47.623,26.421 48.423,26.421 49.223,26.421 50.023,26.421 50.823,26.421 51.623,26.421 54.823,26.421 55.623,26.421 58.823,26.421 49.623,27.221 50.423,27.221 54.423,27.221 55.223,27.221 56.023,27.221 59.223,27.221 50.023,28.021 53.223,28.021 54.023,28.021 54.823,28.021 55.623,28.021 58.823,28.021 49.623,28.821 52.823,28.821 53.623,28.821 54.423,28.821 55.223,28.821 56.023,28.821 56.823,28.821 57.623,28.821 58.423,28.821 59.223,28.821 52.423,29.621 53.223,29.621 54.023,29.621 54.823,29.621 55.623,29.621 56.423,29.621 57.223,29.621 58.023,29.621 58.823,29.621 49.623,30.421 52.023,30.421 52.823,30.421 53.623,30.421 54.423,30.421 55.223,30.421 56.023,30.421 56.823,30.421 57.623,30.421 58.423,30.421 59.223,30.421 46.023,31.221 46.823,31.221 47.623,31.221 48.423,31.221 49.223,31.221 52.423,31.221 53.223,31.221 54.023,31.221 54.823,31.221 55.623,31.221 56.423,31.221 57.223,31.221 58.023,31.221 58.823,31.221 48.823,32.021 49.623,32.021 52.023,32.021 52.823,32.021 53.623,32.021 54.423,32.021 55.223,32.021 56.023,32.021 56.823,32.021 57.623,32.021 58.423,32.021 59.223,32.021 49.223,32.821 52.423,32.821 53.223,32.821 58.023,32.821 58.823,32.821 52.023,33.621 52.823,33.621 53.623,33.621 58.423,33.621 59.223,33.621 52.423,34.421 53.223,34.421 58.023,34.421 58.823,34.421 52.023,35.221 52.823,35.221 53.623,35.221 58.423,35.221 59.223,35.221 52.423,36.021 53.223,36.021 58.023,36.021 58.823,36.021 52.023,36.821 52.823,36.821 53.623,36.821 58.423,36.821 59.223,36.821 52.423,37.621 53.223,37.621 58.023,37.621 58.823,37.621 52.023,38.421 52.823,38.421 53.623,38.421 58.423,38.421 59.223,38.421 49.223,39.221 50.023,39.221 50.823,39.221 51.623,39.221 52.423,39.221 53.223,39.221 54.023,39.221 54.823,39.221 55.623,39.221 56.423,39.221 57.223,39.221 58.023,39.221 58.823,39.221 48.823,40.021 49.623,40.021 50.423,40.021 51.223,40.021 52.023,40.021 52.823,40.021 53.623,40.021 54.423,40.021 55.223,40.021 56.023,40.021 56.823,40.021 57.623,40.021 58.423,40.021 59.223,40.021 49.223,40.821 50.023,40.821 50.823,40.821 51.623,40.821 52.423,40.821 53.223,40.821 54.023,40.821 54.823,40.821 55.623,40.821 56.423,40.821 57.223,40.821 58.023,40.821 58.823,40.821 48.823,41.621 49.623,41.621 50.423,41.621 51.223,41.621 52.023,41.621 52.823,41.621 53.623,41.621 54.423,41.621 55.223,41.621 56.023,41.621 56.823,41.621 57.623,41.621 58.423,41.621 59.223,41.621
  other v2: 49.367,35.247
  other v3: 48.324,27.426 46.393,27.476 47.384,27.476 47.333,28.289 48.298,28.289 46.419,28.315 47.305,29.133 48.247,29.127 46.393,29.153 48.171,29.94 47.282,29.966 46.393,29.991 56.782,33.572 55.944,33.598 54.978,33.649 56.756,34.715 55.055,34.741 55.944,34.741 55.854,35.84 56.756,35.858 55.055,35.884 55.905,37.033 56.782,37.027 55.055,37.052
SW2: C41.2 L2.2 Q4.1 Q4.2 Q4.3 Q6.5-6-7-8 R42.2 U7.18 | length 19
  Top Layer w0.152: v2(66.421,15.646) 66.421,15.686 66.47,15.735 66.47,16.881 C41.2@66.774,17.186
  Top Layer w0.254: U7.18@65.041,14.33 66.349,15.638 66.412,15.638 v2(66.421,15.646)
  Signal Layer 2 w0.5: v2(66.421,15.646) 66.421,22.073 72.442,28.094 ; v1@69.56,35.069 70.035,35.069
  other v1: 65.223,24.821 66.023,24.821 70.023,24.821 70.823,24.821 71.623,24.821 72.423,24.821 73.223,24.821 74.023,24.821 74.823,24.821 75.623,24.821 76.423,24.821 77.223,24.821 61.623,25.621 64.823,25.621 65.623,25.621 66.423,25.621 67.223,25.621 70.423,25.621 71.223,25.621 72.023,25.621 72.823,25.621 73.623,25.621 74.423,25.621 75.223,25.621 77.623,25.621 65.223,26.421 66.023,26.421 66.823,26.421 67.623,26.421 71.623,26.421 72.423,26.421 73.223,26.421 74.023,26.421 61.623,27.221 64.823,27.221 65.623,27.221 66.423,27.221 67.223,27.221 68.023,27.221 68.823,27.221 72.023,27.221 72.823,27.221 73.623,27.221 62.023,28.021 64.423,28.021 65.223,28.021 66.023,28.021 66.823,28.021 67.623,28.021 68.423,28.021 69.223,28.021 73.223,28.021 74.023,28.021 61.623,28.821 62.423,28.821 63.223,28.821 64.023,28.821 64.823,28.821 65.623,28.821 66.423,28.821 67.223,28.821 68.023,28.821 68.823,28.821 69.623,28.821 70.423,28.821 73.623,28.821 74.423,28.821 62.023,29.621 62.823,29.621 63.623,29.621 64.423,29.621 65.223,29.621 66.023,29.621 66.823,29.621 67.623,29.621 68.423,29.621 69.223,29.621 70.023,29.621 70.823,29.621 74.823,29.621 77.223,29.621 61.623,30.421 62.423,30.421 63.223,30.421 64.023,30.421 64.823,30.421 65.623,30.421 66.423,30.421 67.223,30.421 68.023,30.421 68.823,30.421 69.623,30.421 70.423,30.421 71.223,30.421 72.023,30.421 76.023,30.421 76.823,30.421 77.623,30.421 62.023,31.221 62.823,31.221 63.623,31.221 64.423,31.221 65.223,31.221 66.023,31.221 66.823,31.221 67.623,31.221 68.423,31.221 69.223,31.221 70.023,31.221 70.823,31.221 71.623,31.221 72.423,31.221 76.423,31.221 77.223,31.221 61.623,32.021 62.423,32.021 63.223,32.021 64.023,32.021 64.823,32.021 65.623,32.021 66.423,32.021 67.223,32.021 68.023,32.021 68.823,32.021 69.623,32.021 70.423,32.021 71.223,32.021 72.023,32.021 72.823,32.021 62.023,32.821 62.823,32.821 63.623,32.821 64.423,32.821 69.223,32.821 70.023,32.821 70.823,32.821 71.623,32.821 72.423,32.821 73.223,32.821 61.623,33.621 62.423,33.621 63.223,33.621 64.023,33.621 64.823,33.621 69.623,33.621 70.423,33.621 71.223,33.621 72.023,33.621 72.823,33.621 62.023,34.421 62.823,34.421 63.623,34.421 64.423,34.421 70.023,34.421 70.823,34.421 71.623,34.421 72.423,34.421 61.623,35.221 62.423,35.221 63.223,35.221 64.023,35.221 64.823,35.221 69.623,35.221 70.423,35.221 71.223,35.221 72.023,35.221 72.823,35.221 62.023,36.021 62.823,36.021 63.623,36.021 64.423,36.021 70.023,36.021 70.823,36.021 71.623,36.021 72.423,36.021 61.623,36.821 62.423,36.821 63.223,36.821 64.023,36.821 64.823,36.821 69.623,36.821 70.423,36.821 71.223,36.821 72.023,36.821 72.823,36.821 62.023,37.621 62.823,37.621 63.623,37.621 64.423,37.621 70.023,37.621 70.823,37.621 71.623,37.621 72.423,37.621 61.623,38.421 62.423,38.421 63.223,38.421 64.023,38.421 64.823,38.421 69.623,38.421 70.423,38.421 71.223,38.421 72.023,38.421 72.823,38.421 62.023,39.221 62.823,39.221 63.623,39.221 64.423,39.221 65.223,39.221 66.023,39.221 66.823,39.221 67.623,39.221 68.423,39.221 69.223,39.221 70.023,39.221 70.823,39.221 71.623,39.221 72.423,39.221 73.223,39.221 74.023,39.221 61.623,40.021 62.423,40.021 63.223,40.021 64.023,40.021 64.823,40.021 65.623,40.021 66.423,40.021 67.223,40.021 68.023,40.021 68.823,40.021 69.623,40.021 70.423,40.021 71.223,40.021 72.023,40.021 72.823,40.021 73.623,40.021 74.423,40.021 62.023,40.821 62.823,40.821 63.623,40.821 64.423,40.821 65.223,40.821 66.023,40.821 66.823,40.821 67.623,40.821 68.423,40.821 69.223,40.821 70.023,40.821 70.823,40.821 71.623,40.821 72.423,40.821 73.223,40.821 74.023,40.821 61.623,41.621 62.423,41.621 63.223,41.621 64.023,41.621 64.823,41.621 65.623,41.621 66.423,41.621 67.223,41.621 68.023,41.621 68.823,41.621 69.623,41.621 70.423,41.621 71.223,41.621 72.023,41.621 72.823,41.621 73.623,41.621 74.423,41.621
  other v3: 77.309,26.648 75.231,26.673 76.251,26.695 77.259,27.554 76.251,27.61 75.209,27.661 77.241,28.448 75.286,28.473 76.2,28.499 68.038,34.928 65.96,34.953 66.98,34.976 67.988,35.834 66.98,35.89 65.938,35.941 67.97,36.728 66.015,36.754 66.929,36.779
TS: R38.1 R39.2 R40.2 U7.8 | length 10.8
  Top Layer w0.152: R40.2@60.8,8.407 60.8,8.382 R40.2@60.775,8.357 ; R40.2@60.833,8.357 R40.2@60.775,8.357 ; R40.2@60.833,8.433 62.168,8.433 R39.2@62.223,8.377 62.622,8.776 62.622,8.852 63.221,9.45 U7.8@63.221,9.982 ; R38.1@64.11,5.334 63.856,5.588 60.427,5.588 59.842,6.172 59.842,7.449 60.376,7.983 60.401,7.983 R40.2@60.775,8.357
VBUS: C2.1 C80.2 J2.6 L1.1 Q1.5 Q1.6 Q1.7 Q1.8 Q1.9 R56.1 U2.20 | length 54.7
  Top Layer w0.152: v4(14.752,19.384) Q1.9@14.784,19.384 ; J2.6@23.247,25.857 J2.6@23.571,25.857 ; J2.6@23.531,26.141 26.051,26.141 C2.1@26.344,26.434
  Top Layer w0.2: L1.1@11.412,15.429 11.386,15.455 11.386,20.291 C80.2@11.506,20.411 ; 12.446,16.993 13.81,15.628 U2.20@13.81,15.384 ; Q1.9@13.849,18.409 14.007,18.567 14.097,18.567 Q1.9@14.097,18.677 ; Q1.9@14.042,18.622 Q1.9@14.097,18.677 ; Q1.9@14.804,19.384 Q1.9@14.097,18.677
  Signal Layer 2 w0.152: J2.6@23.531,26.141 25.796,23.876 37.77,23.876 39.243,22.403 39.243,14.376 39.446,14.173 54.661,14.173 v2(55.982,12.852)
  other v4: 14.299,18.409 15.204,18.409 15.657,19.384 14.299,20.359 15.204,20.359
  other v5: 13.847,19.384
VBUS_C: C3.2 C4.1 C5.1 J1.A4 J1.A9 J1.B4 J1.B9 L1.2 | length 11.4
  Top Layer w0.2: J1.A9@7.658,12.353 9.001,12.353 9.703,13.056 L1.2@9.703,15.219 ; J1.A4@7.658,14.853 9.337,14.853 L1.2@9.4,14.916 ; C5.1@9.234,20.625 C5.1@9.534,20.325 ; L1.2@9.462,14.853 9.576,14.967 9.576,15.092 9.654,15.17 L1.2@9.703,15.219 ; C3.2@9.612,21.983 C3.2@9.612,22.059 ; L1.2@9.766,15.157 9.912,15.303 L1.2@9.912,15.429 ; L1.2@9.981,15.498 L1.2@9.912,15.429 ; L1.2@9.703,15.219 9.85,15.366 L1.2@9.912,15.429
  Top Layer w0.254: J1.B4@6.058,12.603 6.066,12.595 6.585,12.595 6.827,12.353 J1.A9@7.658,12.353 ; J1.B9@6.058,15.103 6.066,15.095 6.585,15.095 6.827,14.853 J1.A4@7.658,14.853
  other v2: 9.296,17.526
VBUS_LV: C1.1 C15.1 Q1.1 Q1.2 Q1.3 U1.26 U1.27 U2.19 | length 12.1
  Top Layer w0.152: Q1.3@16.999,19.709 18.704,19.709 19.537,18.877 C15.1@19.587,18.877 19.632,18.832 U1.27@21.372,18.832 ; U1.26@21.51,19.232 21.51,18.876 U1.27@21.514,18.872
  Top Layer w0.2: U2.19@14.21,15.384 14.21,16.436 14.178,16.468 14.178,16.573 14.22,16.614 C1.1@14.283,16.678 14.258,16.703 14.156,16.703 14.156,17.255 14.326,17.424 16.612,17.424 16.999,17.812 Q1.1@16.999,18.409 Q1.2@16.999,19.059 Q1.3@16.999,19.709
VIN_3V3: C18.1 R26.1 U1.32 | length 11.7
  Top Layer w0.152: v2(20.371,15.469) 20.38,15.469 20.46,15.549 20.46,15.888 21.311,16.739 21.311,16.808 21.344,16.84 U1.32@21.412,16.84
  Top Layer w0.2: U1.32@21.412,16.832 U1.32@21.51,16.832
  Bottom Layer w0.254: v2(19.609,6.045) 19.863,6.299 19.863,14.961 v2@20.362,15.46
